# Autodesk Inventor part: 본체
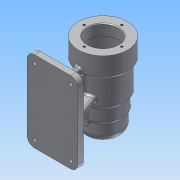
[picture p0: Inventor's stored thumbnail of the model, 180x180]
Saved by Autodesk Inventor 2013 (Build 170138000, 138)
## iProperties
Created: 2016-06
Part Number: 본체
Material: 알루미늄 6061
Document SubType Name: Modeling
Designer: Administrator
Density: 2.71 g/cm^3
Mass: 675.714 g
Surface Area: 653.039 cm^2
Volume: 249.341 cm^3
Author: Administrator
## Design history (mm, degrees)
sketch "스케치1"
  geometry: C1 r 34 at (0, 0); 1 further point
  constraints: 1 centre point, 1 coincident
  dimensions: "d0" = 68 diameter of C1
extrude "돌출1" new body sketch "스케치1" distance "d1" = 28; taper "d2" = 0 deg
sketch "스케치2"
  geometry: C1 r 34 at (0, 0) reference; C2 r 30 at (0, 0)
  constraints: 1 centre point, 1 coincident
  dimensions: "d3" = 60 diameter of C2
extrude "돌출2" join sketch "스케치2" distance "d4" = 39; taper "d5" = 0 deg
sketch "스케치3"
  geometry: C1 r 30 at (0, 0) reference; C2 r 27 at (0, 0)
  constraints: 1 centre point, 1 coincident
  dimensions: "d6" = 54 diameter of C2
extrude "돌출3" join sketch "스케치3" distance "d7" = 20; taper "d8" = 0 deg
sketch "스케치4"
  geometry: C1 r 27 at (0, 0) reference; C2 r 25 at (0, 0)
  constraints: 1 centre point, 1 coincident
  dimensions: "d9" = 50 diameter of C2
extrude "돌출4" join sketch "스케치4" distance "d10" = 25; taper "d11" = 0 deg
node "작업 평면1"
sketch "스케치5"
  geometry: L1 (-25, -84)-(25, -84) reference; L2 (35, -84)-(-35, -84); L3 (-35, -84)-(-35, 28); L4 (-35, 28)-(35, 28); L5 (35, 28)-(35, -84); 2 further points
  constraints: 8 end point, 2 parallel, 1 horizontal, 1 midpoint, 1 perpendicular, 1 vertical alignment
  dimensions: "d13" = 112 distance of L2.end L3.end; "d15" = 70 distance of L3.end L4.end; "d16" = 84 distance from line of point (0, 0) L2
extrude "돌출5" join sketch "스케치5" distance "d17" = 10; taper "d18" = 0 deg
hole "구멍1" diameter "d21" = 42; stored, may be unused: countersink angle "d25" = 90 deg, drill point angle "d27" = 0 deg; dims "d19" = 10, "d20" = 10, "d22" = 6, "d23" = 4, "d24" = 2, "d26" = 15
hole "구멍2" diameter "d30" = 42; stored, may be unused: countersink angle "d34" = 90 deg, drill point angle "d36" = 0 deg; dims "d28" = 10, "d29" = 10, "d31" = 6, "d32" = 48, "d33" = 54, "d35" = 66
hole "구멍3" diameter "d39" = 32; stored, may be unused: countersink angle "d43" = 90 deg, drill point angle "d45" = 0 deg; dims "d37" = 10, "d38" = 10, "d40" = 6, "d41" = 35, "d42" = 18, "d44" = 22
hole "구멍4" diameter "d48" = 21; stored, may be unused: countersink angle "d52" = 90 deg, drill point angle "d54" = 0 deg; dims "d46" = 10, "d47" = 10, "d49" = 6, "d50" = 2, "d51" = 18, "d53" = 3
sketch "스케치6"
  geometry: C1 r 21 at (0, 0) reference; 1 further point
  constraints: 1 vertical alignment
  dimensions: "d55" = 26 distance of C1.centre point (0, 26)
hole "구멍5" sketch "스케치6" at (0, 26) diameter "d56" = 3.242; stored, may be unused: countersink angle "d60" = 90 deg, drill point angle "d62" = 118 deg; dims "d57" = 8, "d58" = 2, "d59" = 18, "d61" = 11
fillet "모깎기1" dims "d66" = 10
sketch "스케치7"
  geometry: A1 r 10 centre (-25, 74) between (-25, 84) and (-35, 74) reference; A2 r 10 centre (-25, -18) between (-35, -18) and (-25, -28) reference; A3 r 10 centre (25, -18) between (25, -28) and (35, -18) reference; A4 r 10 centre (25, 74) between (35, 74) and (25, 84) reference; 5 further points
  constraints: 4 coincident
hole "구멍6" sketch "스케치7" at (-25, 74), (25, 74), (25, -18), (-25, -18) diameter "d67" = 5; stored, may be unused: countersink angle "d71" = 90 deg, drill point angle "d73" = 118 deg; dims "d68" = 8, "d69" = 9, "d70" = 4, "d72" = 11
sketch "스케치8"
  geometry: L1 (-25, -64)-(-60, -64); L2 (-70, 28)-(-60, 28) reference; L3 (-60, -84)-(-70, -84) reference; L4 (-34, 0)-(-34, 28) reference; L5 (-25, -59)-(-25, -84) reference; L6 (-60, -74)-(-60, 18) reference; 1 further point
  constraints: 2 end point, 2 point on line
  dimensions: "d75" = 20 distance between parallel lines of L3 L1
feature "리브1" sketch "스케치8" dims "d76" = 72, "d77" = 8, "d78" = 0, "d79" = 0, "d80" = 1, "d81" = 1
node "작업 평면2"
sketch "스케치9"
  geometry: L1 (-15.509, -25.68)-(-28, -60); L2 (-29.5, -60)-(-20.5, -60) reference; L3 (25, -60)-(-25, -60) reference; A1 r 30 centre (0, 0) between (4, -29.732) and (-4, -29.732) reference; 2 further points
  constraints: 2 end point, 1 point on circle, 1 point on line
  dimensions: "d83" = 110 deg angle of L2 L1; "d84" = 7 distance of L1.end point (-35, -60)
feature "리브2" sketch "스케치9" dims "d85" = 36, "d86" = 8, "d87" = 0, "d88" = 0, "d89" = 1, "d90" = 1
sketch "스케치10"
  geometry: L1 (15.509, -25.68)-(28, -60); L2 (25, -60)-(-25, -60) reference; L3 (20.5, -60)-(29.5, -60) reference; L4 (35, -60)-(35, -70) reference; L5 (25, -60)-(35, -60) reference; A1 r 30 centre (0, 0) between (4, -29.732) and (-4, -29.732) reference; 1 further point
  constraints: 2 end point, 1 point on circle, 1 point on line
  dimensions: "d92" = 7 distance from line of L4 L1.end; "d93" = 110 deg angle of L5 L1
feature "리브3" sketch "스케치10" dims "d94" = 36, "d95" = 8, "d96" = 0, "d97" = 0, "d98" = 1, "d99" = 1
chamfer "모따기1" distance "d100" = 2; stored, may be unused: second distance "d101" = 2, angle "d102" = 45 deg
fillet "모깎기2" dims "d103" = 10, "d104" = 0.3
node "작업 평면3"
sketch "스케치11"
  geometry: L1 (34, 28)-(-34, 28) reference; 3 further points
  constraints: 1 midpoint, 1 vertical alignment, 1 other
  dimensions: "d105" = 48 distance from line of point (0, -20) L1
feature "엠보싱1" sketch "스케치11" dims "d106" = 0.5, "d107" = 0
fillet "모깎기5" dims "d110" = 3
fillet "모깎기6" dims "d111" = 3
chamfer "모따기2" distance "d112" = 1; stored, may be unused: second distance "d113" = 2, angle "d114" = 45 deg
fillet "모깎기7" dims "d115" = 3
fillet "모깎기8" dims "d116" = 3
fillet "모깎기10" dims "d118" = 3, "d119" = 1
fillet "모깎기11" dims "d120" = 3
node "솔리드1"
pattern_circular "원형 패턴1" dims angle "d64" = 360 deg
other parameters: "d82" = -56
